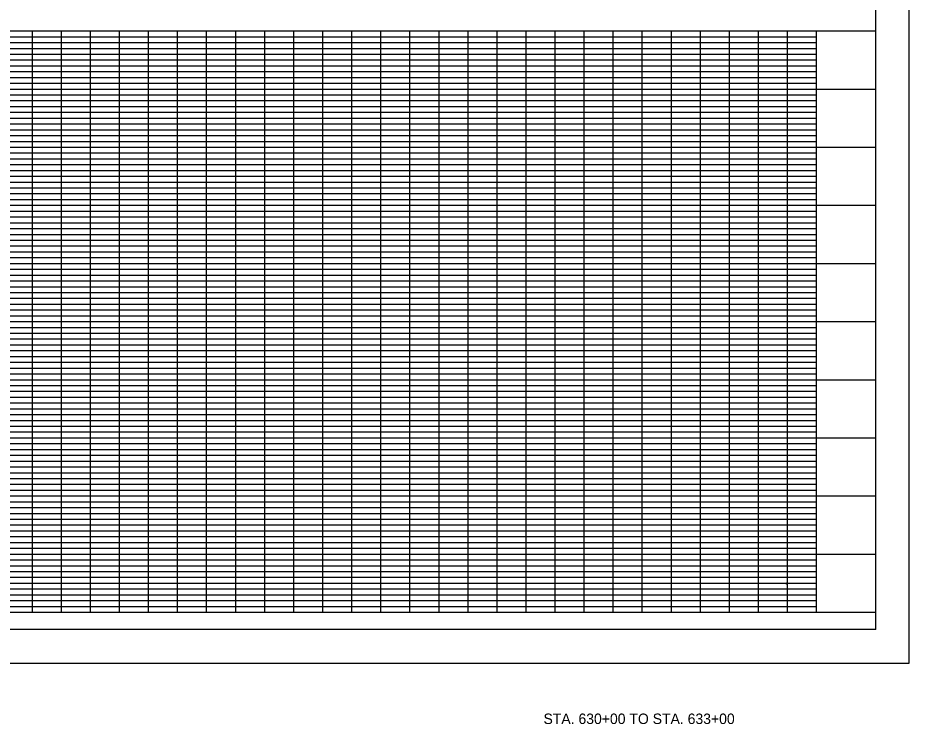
# Model space of a CAD drawing. Extents: x 759422 to 1448857, y 1662254 to 2059437.
# Drawn here: x 1447921 to 1448688, y 2058284 to 2058892 of the extents above; entities that cross this region are included whole.
import ezdxf

# ---------------------------------------------------------------- set-up
doc = ezdxf.new("R2010")
doc.units = 0
for name, color, linetype in [('1', 7, 'Continuous'), ('60', 7, 'Continuous'), ('NO PLOT CELL', 7, 'Continuous')]:
    doc.layers.add(name, color=color, linetype=linetype)

msp = doc.modelspace()

# ---------------------------------------------------------------- linework, layer by layer
at = {"layer": '1'}
for p, q in [((1448659.58, 2058365.37), (1448659.58, 2059407.69)), ((1448659.58, 2058880.07), (1447064.22, 2058880.07)), ((1447933.75, 2058380.07), (1447933.75, 2058880.07)), ((1447958.75, 2058380.07), (1447958.75, 2058880.07)), ((1447983.75, 2058380.07), (1447983.75, 2058880.07)), ((1448008.75, 2058380.07), (1448008.75, 2058880.07)), ((1448033.75, 2058380.07), (1448033.75, 2058880.07)), ((1448058.75, 2058380.07), (1448058.75, 2058880.07)), ((1448083.75, 2058380.07), (1448083.75, 2058880.07)), ((1448108.75, 2058380.07), (1448108.75, 2058880.07)), ((1448133.75, 2058380.07), (1448133.75, 2058880.07)), ((1448158.75, 2058380.07), (1448158.75, 2058880.07)), ((1448183.75, 2058380.07), (1448183.75, 2058880.07)), ((1448208.75, 2058380.07), (1448208.75, 2058880.07)), ((1448233.75, 2058380.07), (1448233.75, 2058880.07)), ((1448258.75, 2058380.07), (1448258.75, 2058880.07)), ((1448283.75, 2058380.07), (1448283.75, 2058880.07)), ((1448308.75, 2058380.07), (1448308.75, 2058880.07)), ((1448333.75, 2058380.07), (1448333.75, 2058880.07)), ((1448358.75, 2058380.07), (1448358.75, 2058880.07)), ((1448383.75, 2058380.07), (1448383.75, 2058880.07)), ((1448408.75, 2058380.07), (1448408.75, 2058880.07)), ((1448433.75, 2058380.07), (1448433.75, 2058880.07)), ((1448458.75, 2058380.07), (1448458.75, 2058880.07)), ((1448483.75, 2058380.07), (1448483.75, 2058880.07)), ((1448508.75, 2058380.07), (1448508.75, 2058880.07)), ((1448533.75, 2058380.07), (1448533.75, 2058880.07)), ((1448558.75, 2058380.07), (1448558.75, 2058880.07)), ((1448583.75, 2058380.07), (1448583.75, 2058880.07)), ((1448608.75, 2058380.07), (1448608.75, 2058880.07)), ((1448608.75, 2058875.07), (1447108.75, 2058875.07)), ((1448608.75, 2058870.07), (1447108.75, 2058870.07)), ((1448608.75, 2058865.07), (1447108.75, 2058865.07)), ((1448608.75, 2058860.07), (1447108.75, 2058860.07)), ((1448608.75, 2058855.07), (1447108.75, 2058855.07)), ((1448608.75, 2058850.07), (1447108.75, 2058850.07)), ((1448608.75, 2058845.07), (1447108.75, 2058845.07)), ((1448608.75, 2058840.07), (1447108.75, 2058840.07)), ((1448608.75, 2058835.07), (1447108.75, 2058835.07)), ((1448659.58, 2058830.07), (1447064.22, 2058830.07)), ((1448608.75, 2058825.07), (1447108.75, 2058825.07)), ((1448608.75, 2058820.07), (1447108.75, 2058820.07)), ((1448608.75, 2058815.07), (1447108.75, 2058815.07)), ((1448608.75, 2058810.07), (1447108.75, 2058810.07)), ((1448608.75, 2058805.07), (1447108.75, 2058805.07)), ((1448608.75, 2058800.07), (1447108.75, 2058800.07)), ((1448608.75, 2058795.07), (1447108.75, 2058795.07)), ((1448608.75, 2058790.07), (1447108.75, 2058790.07)), ((1448659.58, 2058780.07), (1447064.22, 2058780.07)), ((1448608.75, 2058785.07), (1447108.75, 2058785.07)), ((1448608.75, 2058775.07), (1447108.75, 2058775.07)), ((1448608.75, 2058770.07), (1447108.75, 2058770.07)), ((1448608.75, 2058765.07), (1447108.75, 2058765.07)), ((1448608.75, 2058760.07), (1447108.75, 2058760.07)), ((1448608.75, 2058755.07), (1447108.75, 2058755.07)), ((1448608.75, 2058750.07), (1447108.75, 2058750.07)), ((1448608.75, 2058745.07), (1447108.75, 2058745.07)), ((1448608.75, 2058740.07), (1447108.75, 2058740.07)), ((1448608.75, 2058735.07), (1447108.75, 2058735.07)), ((1448659.58, 2058730.07), (1447064.22, 2058730.07)), ((1448608.75, 2058725.07), (1447108.75, 2058725.07)), ((1448608.75, 2058720.07), (1447108.75, 2058720.07)), ((1448608.75, 2058715.07), (1447108.75, 2058715.07)), ((1448608.75, 2058710.07), (1447108.75, 2058710.07)), ((1448608.75, 2058705.07), (1447108.75, 2058705.07)), ((1448608.75, 2058700.07), (1447108.75, 2058700.07)), ((1448608.75, 2058695.07), (1447108.75, 2058695.07)), ((1448608.75, 2058690.07), (1447108.75, 2058690.07)), ((1448659.58, 2058680.07), (1447064.22, 2058680.07)), ((1448608.75, 2058685.07), (1447108.75, 2058685.07)), ((1448608.75, 2058675.07), (1447108.75, 2058675.07)), ((1448608.75, 2058670.07), (1447108.75, 2058670.07)), ((1448608.75, 2058665.07), (1447108.75, 2058665.07)), ((1448608.75, 2058660.07), (1447108.75, 2058660.07)), ((1448608.75, 2058655.07), (1447108.75, 2058655.07)), ((1448608.75, 2058650.07), (1447108.75, 2058650.07)), ((1448608.75, 2058645.07), (1447108.75, 2058645.07)), ((1448608.75, 2058640.07), (1447108.75, 2058640.07)), ((1448608.75, 2058635.07), (1447108.75, 2058635.07)), ((1448659.58, 2058630.07), (1447064.22, 2058630.07)), ((1448608.75, 2058625.07), (1447108.75, 2058625.07)), ((1448608.75, 2058620.07), (1447108.75, 2058620.07)), ((1448608.75, 2058615.07), (1447108.75, 2058615.07)), ((1448608.75, 2058610.07), (1447108.75, 2058610.07)), ((1448608.75, 2058605.07), (1447108.75, 2058605.07)), ((1448608.75, 2058600.07), (1447108.75, 2058600.07)), ((1448608.75, 2058595.07), (1447108.75, 2058595.07)), ((1448608.75, 2058590.07), (1447108.75, 2058590.07)), ((1448659.58, 2058580.07), (1447064.22, 2058580.07)), ((1448608.75, 2058585.07), (1447108.75, 2058585.07)), ((1448608.75, 2058575.07), (1447108.75, 2058575.07)), ((1448608.75, 2058570.07), (1447108.75, 2058570.07)), ((1448608.75, 2058565.07), (1447108.75, 2058565.07)), ((1448608.75, 2058560.07), (1447108.75, 2058560.07)), ((1448608.75, 2058555.07), (1447108.75, 2058555.07)), ((1448608.75, 2058550.07), (1447108.75, 2058550.07)), ((1448608.75, 2058545.07), (1447108.75, 2058545.07)), ((1448608.75, 2058540.07), (1447108.75, 2058540.07)), ((1448608.75, 2058535.07), (1447108.75, 2058535.07)), ((1448659.58, 2058530.07), (1447064.22, 2058530.07)), ((1448608.75, 2058525.07), (1447108.75, 2058525.07)), ((1448608.75, 2058520.07), (1447108.75, 2058520.07)), ((1448608.75, 2058515.07), (1447108.75, 2058515.07)), ((1448608.75, 2058510.07), (1447108.75, 2058510.07)), ((1448608.75, 2058505.07), (1447108.75, 2058505.07)), ((1448608.75, 2058500.07), (1447108.75, 2058500.07)), ((1448608.75, 2058495.07), (1447108.75, 2058495.07)), ((1448608.75, 2058490.07), (1447108.75, 2058490.07)), ((1448659.58, 2058480.07), (1447064.22, 2058480.07)), ((1448608.75, 2058485.07), (1447108.75, 2058485.07)), ((1448608.75, 2058475.07), (1447108.75, 2058475.07)), ((1448608.75, 2058470.07), (1447108.75, 2058470.07)), ((1448608.75, 2058465.07), (1447108.75, 2058465.07)), ((1448608.75, 2058460.07), (1447108.75, 2058460.07)), ((1448608.75, 2058455.07), (1447108.75, 2058455.07)), ((1448608.75, 2058450.07), (1447108.75, 2058450.07)), ((1448608.75, 2058445.07), (1447108.75, 2058445.07)), ((1448608.75, 2058440.07), (1447108.75, 2058440.07)), ((1448608.75, 2058435.07), (1447108.75, 2058435.07)), ((1448659.58, 2058430.07), (1447064.22, 2058430.07)), ((1448608.75, 2058425.07), (1447108.75, 2058425.07)), ((1448608.75, 2058420.07), (1447108.75, 2058420.07)), ((1448608.75, 2058415.07), (1447108.75, 2058415.07)), ((1448608.75, 2058410.07), (1447108.75, 2058410.07)), ((1448608.75, 2058405.07), (1447108.75, 2058405.07)), ((1448608.75, 2058400.07), (1447108.75, 2058400.07)), ((1448608.75, 2058395.07), (1447108.75, 2058395.07)), ((1448608.75, 2058390.07), (1447108.75, 2058390.07)), ((1448659.58, 2058380.07), (1447064.22, 2058380.07)), ((1448608.75, 2058385.07), (1447108.75, 2058385.07)), ((1448659.58, 2058365.37), (1447064.22, 2058365.37))]:
    msp.add_line(p, q, dxfattribs=at)
msp.add_lwpolyline([(1448688.42, 2059436.53), (1446988.42, 2059436.53), (1446988.42, 2058336.53), (1448688.42, 2058336.53)], close=True, dxfattribs=at)
at = {"layer": 'NO PLOT CELL'}
msp.add_circle((1448582.92, 2058405.07), 0.5, dxfattribs=at)

# ---------------------------------------------------------------- texts
at = {"layer": '60'}
msp.add_text('STA. 630+00 TO STA. 633+00', height=9, dxfattribs=at).set_placement((1448373.68, 2058284.16))

doc.saveas('drawing.dxf')
